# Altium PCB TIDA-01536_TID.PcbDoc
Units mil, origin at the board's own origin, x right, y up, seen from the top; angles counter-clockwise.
Board outline 2552 x 2000 mil, 2 copper layers (Top Layer, Bottom Layer), stack 62 mil thick; 52 components, 29 nets, 137 pads, 92 vias.
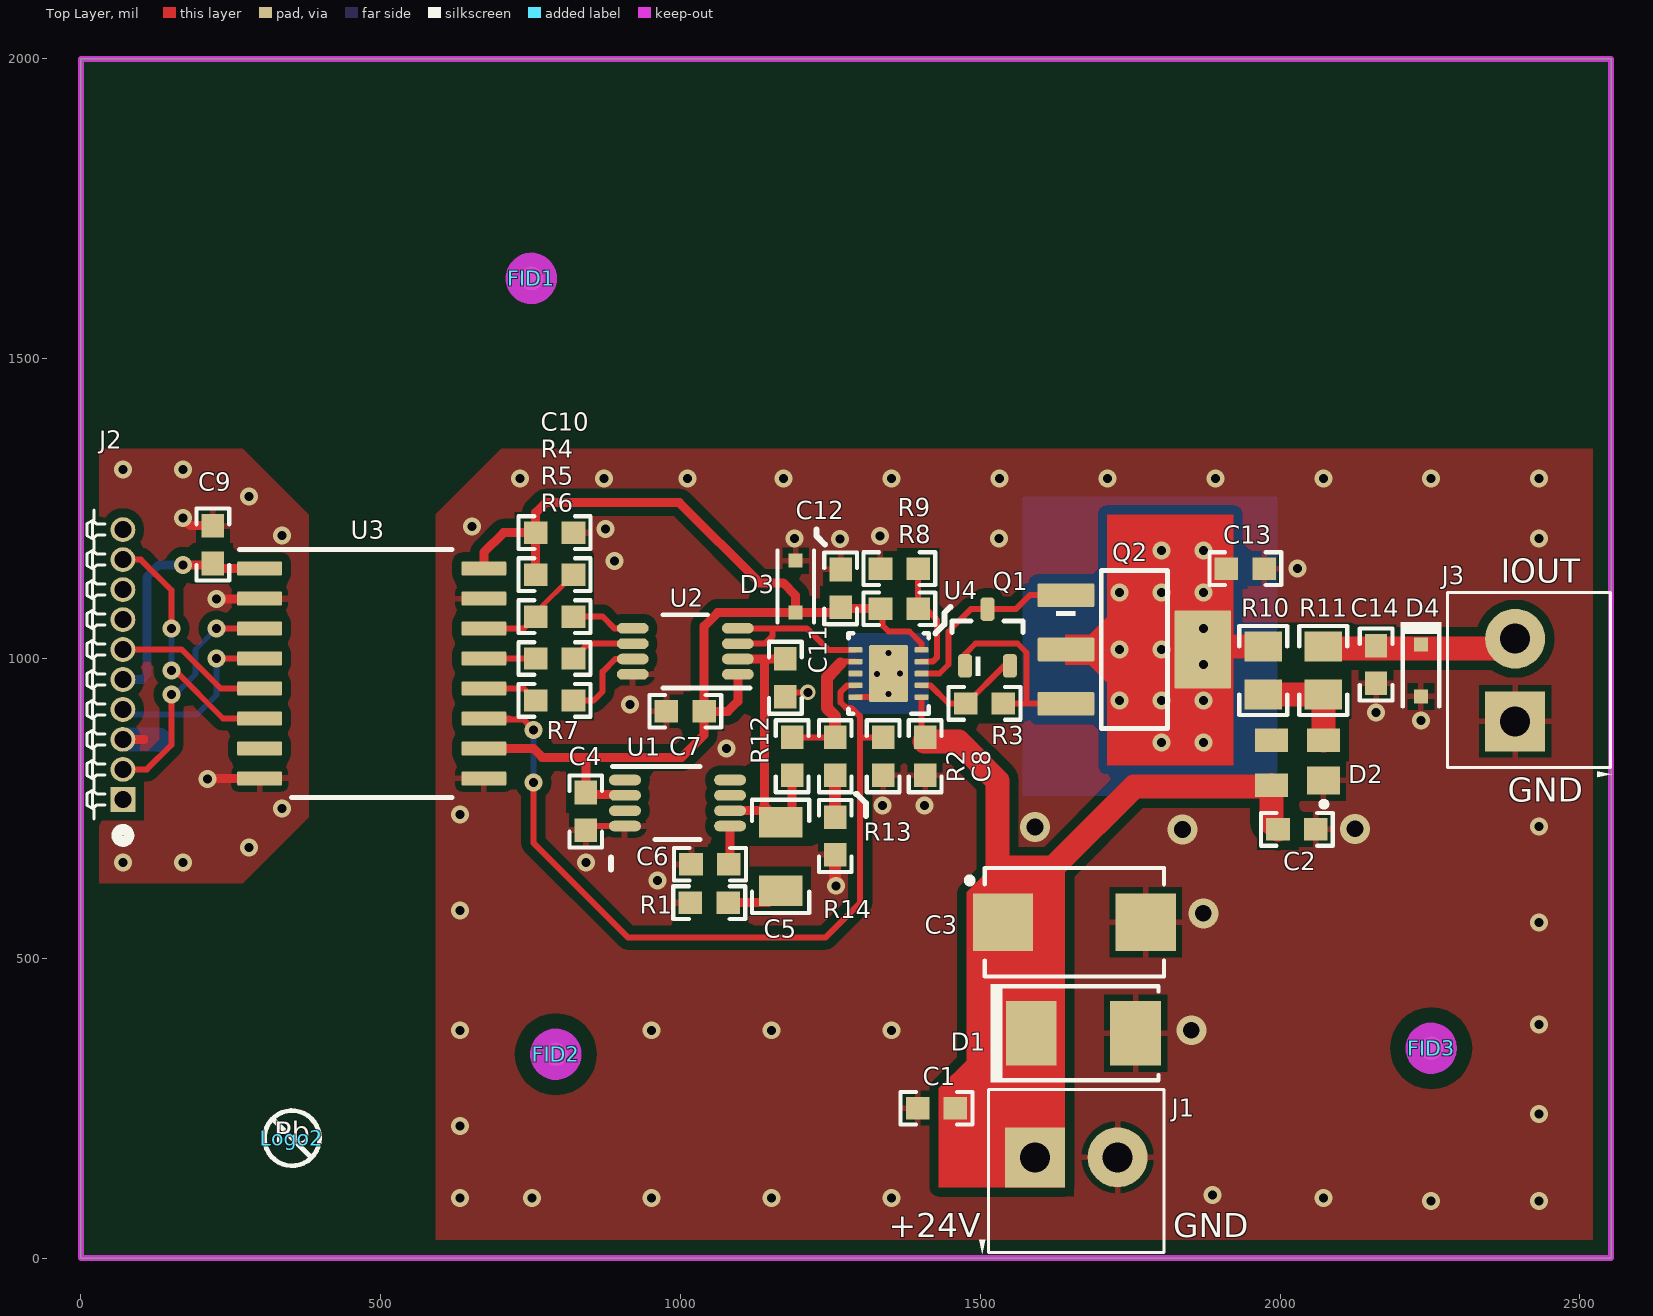
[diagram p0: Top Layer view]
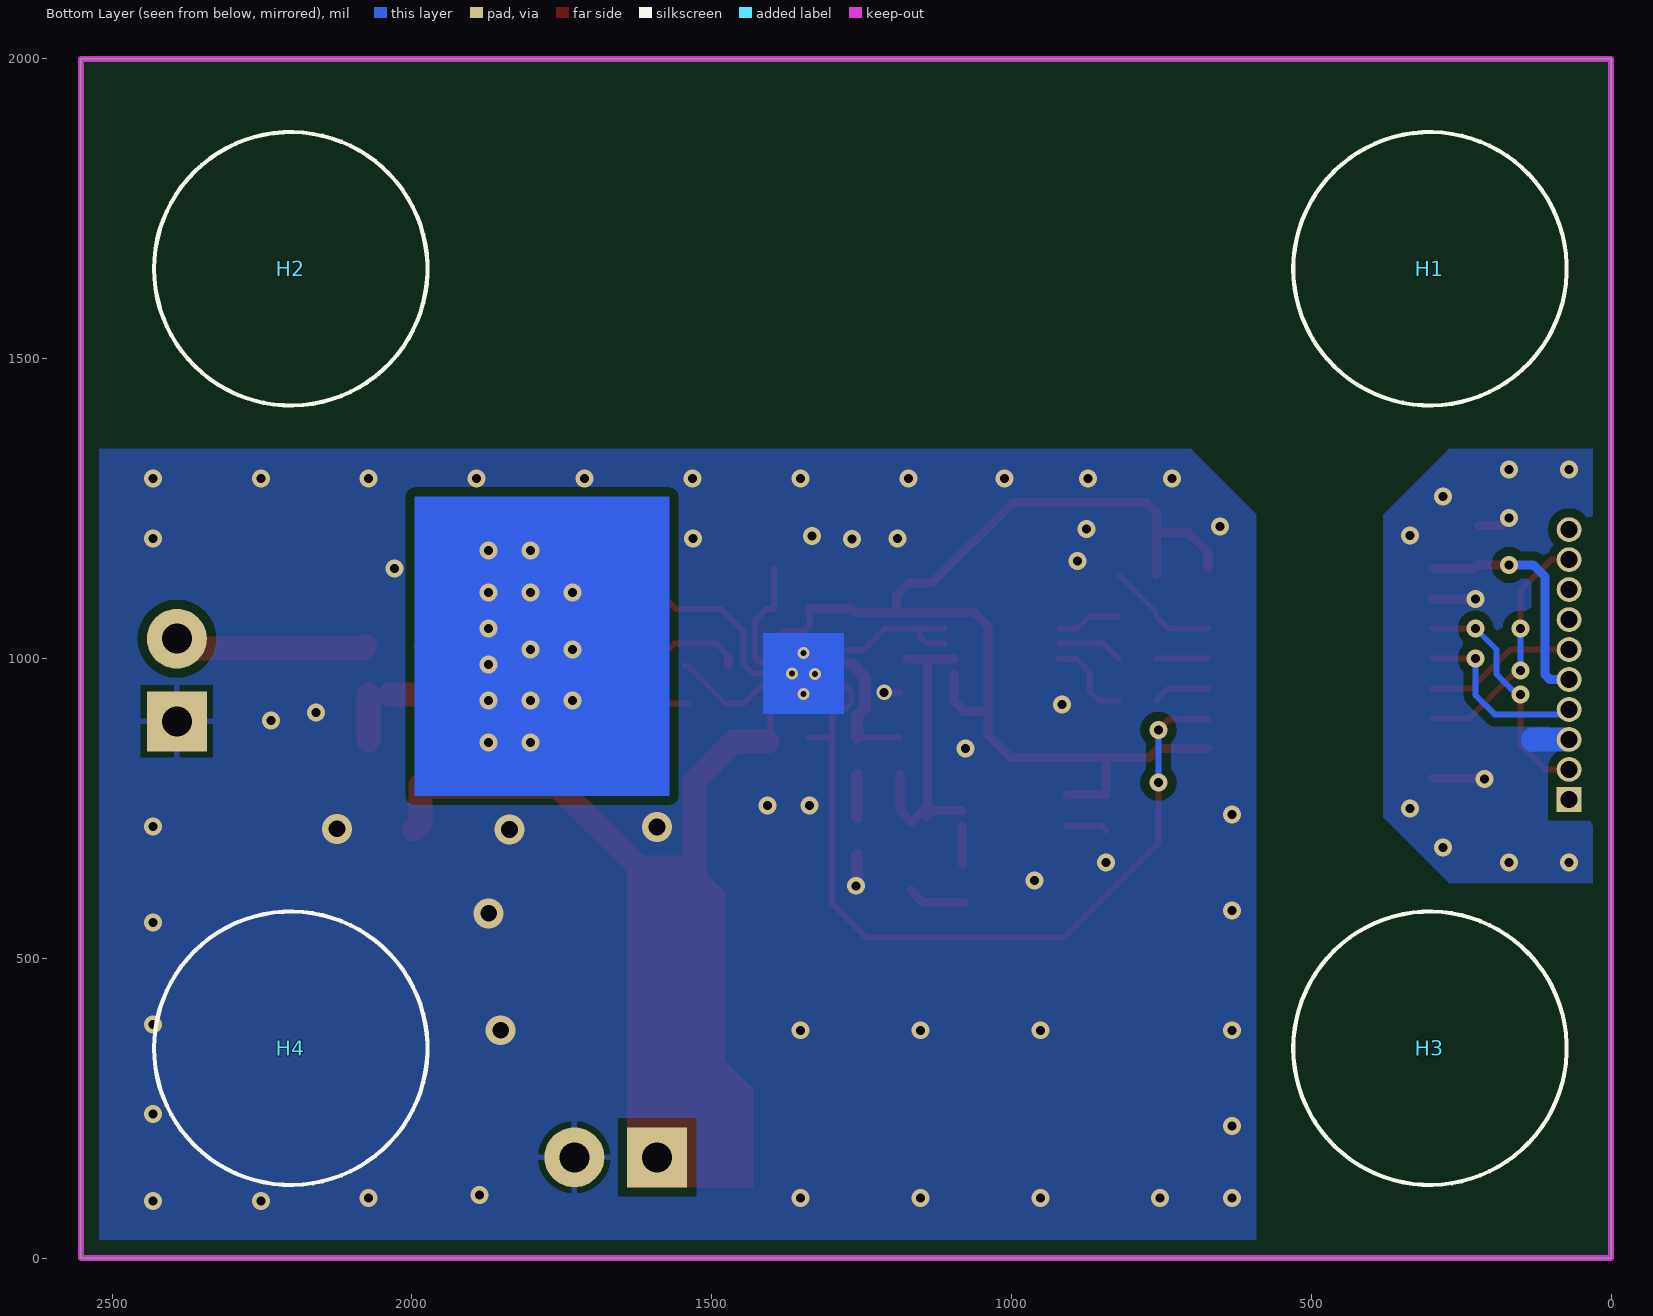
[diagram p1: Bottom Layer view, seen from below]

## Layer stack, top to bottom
Top Solder: solder mask 0.4, Solder Resist, Dk 3.5
Top Layer: signal copper 1.4
Dielectric1: core 59.2, FR-4, Dk 4.8
Bottom Layer: signal copper 1.4
Bottom Solder: solder mask 0.4, Solder Resist, Dk 3.5

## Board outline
0,0 0,2000 2552,2000 2552,0

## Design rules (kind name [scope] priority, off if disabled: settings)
AcuteAngle [All] p1: minimum=4.50000000000000E+0001 checktracksonly=FALSE
AssemblyTestPointUsage [All] p1: valid=2
Clearance Clearance_Keepouts [((IsTrack Or IsArc) And Not InPoly) And IsFree and IsKeepOut vs ((IsTrack Or IsArc) And Not InPoly) And IsFree and IsKeepOut] p1: gap=0 ignorepadtopadclearanceinfootprint=FALSE
Clearance Clearance_BoardEdge_MountingHoles [OnCopper and InComponentClass('Mounting Holes') vs IsKeepOut] p2: gap=40 ignorepadtopadclearanceinfootprint=FALSE except(0: Arc-Hole Track-Hole SMDPad-Hole THPad-Hole Via-Hole Fill-Hole Poly-Hole Region-Hole Text-Hole)
Clearance Clearance_BoardEdge_Poly [OnCopper and InPoly vs IsKeepOut] p3: gap=25 ignorepadtopadclearanceinfootprint=FALSE except(0: Arc-Hole Track-Hole SMDPad-Hole THPad-Hole Via-Hole Fill-Hole Poly-Hole Region-Hole Text-Hole)
Clearance Clearance_BoardEdge [OnCopper and Not InComponentClass('Logo') and not InComponentClass('FiducialMark') and not InRegion(1000,500,4000,800) and Not IsKeepout vs IsKeepOut] p4: gap=75 ignorepadtopadclearanceinfootprint=FALSE except(0: Arc-Hole Track-Hole SMDPad-Hole THPad-Hole Via-Hole Fill-Hole Poly-Hole Region-Hole Text-Hole)
Clearance Clearance_Poly [InPolygon] p5: gap=15 ignorepadtopadclearanceinfootprint=FALSE except(0: Arc-Hole Track-Hole SMDPad-Hole THPad-Hole Via-Hole Fill-Hole Poly-Hole Region-Hole Text-Hole)
Clearance [All] p6: gap=7.87 ignorepadtopadclearanceinfootprint=FALSE except(0: Arc-Hole Track-Hole SMDPad-Hole THPad-Hole Via-Hole Fill-Hole Poly-Hole Region-Hole Text-Hole)
ComponentClearance ComponentClearance_MountingHoles_FiducialMarks [InComponentClass('Mounting Holes') vs InComponentClass('FiducialMark')] p1: gap=50 collisioncheckmode=3 verticalgap=10 showdistances=FALSE
ComponentClearance ComponentClearance_Shunt [InComponentClass('Header') vs InComponentClass('Shunt')] p2: gap=0 collisioncheckmode=3 verticalgap=0 showdistances=FALSE
ComponentClearance ComponentClearance_Logo [InComponentClass('Logo')] p3: gap=50 collisioncheckmode=3 verticalgap=10 showdistances=FALSE
ComponentClearance ComponentClearance_ScrewToNut [(HasFootprint('NY PMS 440 0025 PH')) vs (HasFootprint('Keystone_1902C'))] p4: gap=5 collisioncheckmode=3 verticalgap=10 showdistances=FALSE
ComponentClearance ComponentClearance_MountingHoles [InComponentClass('Mounting Holes')] p5: gap=250 collisioncheckmode=3 verticalgap=100000 showdistances=FALSE
ComponentClearance ComponentClearance_SmallPassives [HasFootprint('0201*') or HasFootprint('0402*') or HasFootprint('0508') or HasFootprint('0603*') or HasFootprint('0612') or HasFootprint('0805*') or HasFootprint('0815*') or HasFootprint('0830*') or HasFootprint('1206*') or HasFootprint('1210*') or HasFootprint('1808*') or HasFootprint('1812*') or HasFootprint('1825*') or HasFootprint('2010*') or HasFootprint('2220*') or HasFootprint('2225*') or HasFootprint('2512*') or HasFootprint('2728*') or HasFootprint('3518*') vs HasFootprint('0201*') or HasFootprint('0402*') or HasFootprint('0508') or HasFootprint('0603*') or HasFootprint('0612') or HasFootprint('0805*') or HasFootprint('0815*') or HasFootprint('0830*') or HasFootprint('1206*') or HasFootprint('1210*') or HasFootprint('1808*') or HasFootprint('1812*') or HasFootprint('1825*') or HasFootprint('2010*') or HasFootprint('2220*') or HasFootprint('2225*') or HasFootprint('2512*') or HasFootprint('2728*') or HasFootprint('3518*')] p6: gap=20 collisioncheckmode=3 verticalgap=10 showdistances=FALSE
ComponentClearance ComponentClearance_THtoSMT [IsThruComponent vs IsSMTComponent] p7: gap=20 collisioncheckmode=3 verticalgap=30 showdistances=FALSE
ComponentClearance ComponentClearance_THtoTH [IsThruComponent vs IsThruComponent] p8: gap=20 collisioncheckmode=3 verticalgap=30 showdistances=FALSE
ComponentClearance [All] p9: gap=20 collisioncheckmode=3 verticalgap=10 showdistances=FALSE
DiffPairsRouting [All] p1: maxlimit=100 minlimit=10 mostfreqgap=10 toplayer_minwidth=15 toplayer_maxwidth=15 toplayer_prefwidth=15 bottomlayer_minwidth=15 bottomlayer_maxwidth=15 bottomlayer_prefwidth=15 maxuncoupledlength=1000
FabricationTestPointUsage TestPointUsage [All] p1: valid=2 allowmultiple=FALSE
FabricationTestpoint Testpoint [All] p1: side=3 testpointundercomponent=TRUE minsize=40 maxsize=100 preferedsize=60 minholesize=0 maxholesize=40 preferedholesize=32 testpointgrid=1 allowsidetop=TRUE allowsidebottom=TRUE usegrid=TRUE gridtolerance=0.01
FanoutControl Fanout_LCC [IsLCC] p1: bgadir=Out bgaviamode=Centered fanoutstyle=Auto fanoutdirection=Alternating viagrid=1 // Fanout_LCC (Default Rule)
FanoutControl Fanout_BGA [IsBGA] p2: bgadir=Out bgaviamode=Centered fanoutstyle=Auto fanoutdirection=Alternating viagrid=1 // Fanout_BGA (Default Rule)
FanoutControl Fanout_Default [All] p4: bgadir=Out bgaviamode=Centered fanoutstyle=Auto fanoutdirection=Alternating viagrid=1 // Fanout_Default (Default Rule)
FanoutControl Fanout_Small [(CompPinCount < 5)] p5: bgadir=Out bgaviamode=Centered fanoutstyle=Auto fanoutdirection=OutThenIn viagrid=1 // Fanout_Small (Default Rule)
HoleSize [All] p1: absolutevalues=TRUE maxlimit=251 minlimit=8 maxpercent=80.000 minpercent=20.000
MinimumAnnularRing MinimumAnnularRing_ThermalPadVias [IsVia and InAnyComponent] p1: minimumring=5.91
MinimumAnnularRing [All] p2: minimumring=9
MinimumSolderMaskSliver MinimumSolderMaskSliver_Logo [InComponentClass('Logo') vs InComponentClass('Logo')] p1: minsoldermaskwidth=0.7
MinimumSolderMaskSliver [All] p2: minsoldermaskwidth=3.94
PlaneConnect [All] p1: planeconnectstyle=Relief reliefexpansion=10 reliefentries=4 reliefconductorwidth=10 reliefairgap=10
PolygonConnect PolygonConnect_1 [(InComponentClass('All Components'))] p1: connectstyle=Relief reliefconductorwidth=10 reliefentries=4 polygonreliefangle="90 Angle" airgapwidth=10
PolygonConnect [All] p2: connectstyle=Direct reliefconductorwidth=10 reliefentries=4 polygonreliefangle="90 Angle" airgapwidth=10
RoutingVias ThermalPadVias [IsVia and InAnyComponent] p1: holewidth=7.87 width=19.68 viastyle="Through Hole" minholewidth=7.87 minwidth=19.68 maxholewidth=12.99 maxwidth=23.62
RoutingVias [All] p2: holewidth=16 width=34 viastyle="Through Hole" minholewidth=7.87 minwidth=26 maxholewidth=40 maxwidth=65
SilkToBoardRegionClearance [Not ((IsComment or IsDesignator) And (Hide <> 'False')) and not InRegion(1000,500,4000,800)] p1:
SilkToSilkClearance SilkToSilkClearance_Pb-FreeLogo [(HasFootprint('Pb-Free_Overlay_Medium') OR HasFootprint('Pb-Free_Overlay_Small')) vs (HasFootprint('Pb-Free_Overlay_Medium') OR HasFootprint('Pb-Free_Overlay_Small'))] p1: silktosilkclearance=0
SilkToSilkClearance [All] p2: silktosilkclearance=4
SilkToSolderMaskClearance SilkToComonentPadClearance [IsPad and InAnycomponent] p1: minsilkscreentomaskgap=5 clearancetoexposedcopper=TRUE
SilkToSolderMaskClearance "Silk to Solder Mask Opening" [All] p2: minsilkscreentomaskgap=4 clearancetoexposedcopper=FALSE
SolderMaskExpansion [All] p1: expansion=1.97
Width [All] p1: maxlimit=100 minlimit=6 preferedwidth=10 checkconnectedcopper=TRUE
15 further rules are at their usual default settings.

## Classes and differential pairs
component class TIDA-01536_BlankSheet: C1 C2 C3 C4 C5 C6 C7 C8 C9 C10 C11 C12 C13 C14 D1 D2 D3 D4 J1 J2 J3 Q1 Q2 R1 R2 R3 R4 R5 R6 R7 R8 R9 R10 R11 R12 R13 R14 U1 U2 U3 U4
component class AssemblyNote: ZZ1 ZZ2 ZZ3
component class FiducialMark: FID1 FID2 FID3
component class TIPD203_TID_Hardware: FID1 FID2 FID3 H1 H2 H3 H4 Logo2 ZZ1 ZZ2 ZZ3

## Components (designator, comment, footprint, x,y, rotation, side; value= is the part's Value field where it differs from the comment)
C1 "GRM188R71H104KA93D" 0603 1427,250 r0 top value=0.1uF
C2 "06035A101JAT2A" 0603 2028,715 r0 top value=100pF
C3 "293D106X9050E2TE3" 7343-43 1657,560 r0 top value=10uF
C4 "GRM188R71E105KA12D" 0603 842,745 r270 top value=1uF
C5 "GRM31CR61C226ME15L" 1206 1167,670 r270 top value=22uF
C6 "GRM188R71E105KA12D" 0603 1049,657 r180 top value=1uF
C7 "GRM188R71E105KA12D" 0603 1008,912 r180 top value=1uF
C8 "GRM188R71E105KA12D" 0603 1408,837 r270 top value=1uF
C9 "GRM188R71E105KA12D" 0603 220,1190 r90 top value=1uF
C10 "GRM188R71E105KA12D" 0603 790,1210 r0 top value=1uF
C11 "GRM188R71E105KA12D" 0603 1175,968 r270 top value=1uF
C12 "GRM188R71E105KA12D" 0603 1267,1117 r90 top value=1uF
C13 "GRM188R72A103KA01D" 0603 1942,1150 r0 top value=0.01uF
C14 "GRM188R71H104KA93D" 0603 2160,990 r270 top value=0.1uF
D1 "SMBJ24A-13-F" SMB 1672,375 r0 top value=24V
D2 "CD143A-SR70" SOT-143-4 2029,832 r180 top
D3 "CDSOD323-T05" SOD-323-Bi 1192,1120 r270 top value=5V
D4 "CDSOD323-T24S" sod-323 2235,980 r270 top
FID1 "Fiducial" Fiducial10-20 751,1634 r0 top
FID2 "Fiducial" Fiducial10-20 792,340 r0 top
FID3 "Fiducial" Fiducial10-20 2252,350 r0 top
H1 "SJ-5303 (CLEAR)" Bumpon_SJ5003Transparent 302,1650 r180 bottom
H2 "SJ-5303 (CLEAR)" Bumpon_SJ5003Transparent 2202,1650 r180 bottom
H3 "SJ-5303 (CLEAR)" Bumpon_SJ5003Transparent 302,350 r180 bottom
H4 "SJ-5303 (CLEAR)" Bumpon_SJ5003Transparent 2202,350 r180 bottom
J1 "ED555/2DS" TERM_BLK_ED555-2DS 1591,168 r0 top
J2 "SUPER MINI DIG FEMALE" CONN_851-43-010-20-001000 70,990 r270 top
J3 "ED555/2DS" TERM_BLK_ED555-2DS 2392,895 r90 top
Logo2 "Pb-Free Symbol" Pb-Free_Overlay_Small 352,200 r0 top
Q1 "BC856B-7-F" SOT-23 1512,1035 r90 top value="65 V"
Q2 "NDT2955" SOT-223 1757,1015 r0 top value=-60V
R1 "CRCW06031R00JNEA" 0603 1048,593 r0 top value=1.0
R2 "CRCW0603100KFKEA" 0603 1338,837 r90 top value=100k
R3 "CRCW060315R0FKEA" 0603 1507,925 r0 top value=15.0
R4 "RC0603FR-0710KL" 0603 790,1140 r180 top value=10.0k
R5 "CRCW060333R0FKEA" 0603 790,1070 r0 top value=33.0
R6 "CRCW060333R0FKEA" 0603 790,1000 r0 top value=33.0
R7 "CRCW060333R0FKEA" 0603 790,930 r0 top value=33.0
R8 "RG1608P-8251-B-T5" 0603 1365,1083 r0 top value=8.25k
R9 "RG1608P-103-B-T5" 0603 1365,1150 r180 top value=10.0k
R10 "CRCW080515R0FKEA" 0805_HV 1972,980 r270 top value=15.0
R11 "CRCW080515R0FKEA" 0805_HV 2072,980 r90 top value=15.0
R12 "RG1608P-3093-B-T5" 0603 1186,837 r270 top value=309k
R13 "RG1608P-2431-B-T5" 0603 1258,837 r90 top value=2.43k
R14 "2-1676481-2" 0603 1258,704 r90 top value=39.0
U1 "REF5050AIDGKT" DGK0008A_N 995,759 r0 top
U2 "DAC8551IDGKR" DGK0008A_N 1008,1012 r180 top
U3 "ISO7340CDWR" DW0016B_N 485,975 r0 top
U4 "XTR111AIDRCT" DRC0010A 1347,975 r180 top
ZZ1 "These assemblies are ESD sensitive, ESD precautions shall be observed." AssemblyNote 137,3829.11 r0 top
ZZ2 "These assemblies must be clean and free from flux and all contaminants. Use of no clean flux is not acceptable." AssemblyNote 137,3740.56 r0 top
ZZ3 "These assemblies must comply with workmanship standards IPC-A-610 Class 2, unless otherwise specified." AssemblyNote 137,3652 r0 top

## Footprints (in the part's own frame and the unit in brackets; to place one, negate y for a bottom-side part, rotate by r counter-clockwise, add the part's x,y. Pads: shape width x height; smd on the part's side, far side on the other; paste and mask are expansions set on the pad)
0603 [mm] "0603 from SM-752 data"
  rect 1x0.95 smd: 1(-0.8,0) 2(0.8,0)
  silkscreen extent -1.52,-0.69 1.52,0.69, body extent -0.87,-0.47 0.87,0.47, height 1
0805_HV [mil] "0805 with 30mil clearance between pads"
  rect 50x63 smd: 1(-40,0) 2(40,0)
  silkscreen extent -74,-40 74,40, body extent -43,-29 43,29, height 57
1206 [mm] "1206 from SM-752 data"
  rect 1.3x1.85 smd: 1(-1.45,0) 2(1.45,0)
  silkscreen extent -2.4,-1.21 2.4,1.21, body extent -1.7,-0.9 1.7,0.9, height 1.35
7343-43 [mm] "Medium density IPC based on Kemet T495 series"
  rect 2.55x2.45 smd: 1(-3.025,0) 2(3.025,0)
  silkscreen extent -4.56,-2.3 3.8,2.3, body extent -3.8,-2.3 3.8,2.3, height 4.3
AssemblyNote [mil] "Assembly Note"
Bumpon_SJ5003Transparent [mil] "3M Hemispherical Bumpon transparent"
  round 1 on Mech4: 0(0,0)
  silkscreen extent -228,-228 228,228, body extent -217,-218 219,218, height 197
CONN_851-43-010-20-001000 [mm] "Mill-max"
  rect 1.05x1.05 hole 0.73 mask+0.06: 1(5.715,0)
  round 1.05 hole 0.73 mask+0.06: 2(4.445,0) 3(3.175,0) 4(1.905,0) 5(0.635,0) 6(-0.635,0) 7(-1.905,0) 8(-3.175,0) 9(-4.445,0) 10(-5.715,0)
  silkscreen extent -6.54,-1.52 7.49,0.25, body extent -6.54,-5.31 6.54,0.23, height 2.23
DGK0008A_N [mm] "TSOP, 8-Leads, Body 3x3mm, Pitch 0.65mm, IPC Medium Density"
  oval 1.35x0.45 smd: 1(-2.225,0.975) 2(-2.225,0.325) 3(-2.225,-0.325) 4(-2.225,-0.975) 5(2.225,-0.975) 6(2.225,-0.325) 7(2.225,0.325) 8(2.225,0.975)
  silkscreen extent -2.75,-1.55 0.95,1.55, body extent -2.45,-1.5 2.45,1.5, height 0.96
DRC0010A [mm] "SON, 10-Leads, Body 3x3mm, Pitch 0.5mm, Thermal Pad 2.4x1.65mm, TI Recommended"
  rrect42% 0.6x0.24 smd: 1(-1.4,1) 2(-1.4,0.5) 3(-1.4,0) 4(-1.4,-0.5) 5(-1.4,-1) 6(1.4,-1) 7(1.4,-0.5) 8(1.4,0) 9(1.4,0.5) 10(1.4,1)
  rrect6% 1.65x2.4 smd paste-0.825: 11(0,0)
  silkscreen extent -1.7,-1.7 1.7,1.7, body extent -1.55,-1.55 1.55,1.55, height 1.01
DW0016B_N [mm] "SOIC, 16-Leads, Body 10.5x7.6mm, Pitch 1.27mm, IPC Medium Density"
  rrect17% 1.9x0.6 smd: 1(-4.75,4.445) 2(-4.75,3.175) 3(-4.75,1.905) 4(-4.75,0.635) 5(-4.75,-0.635) 6(-4.75,-1.905) 7(-4.75,-3.175) 8(-4.75,-4.445) 9(4.75,-4.445) 10(4.75,-3.175) 11(4.75,-1.905) 12(4.75,-0.635) 13(4.75,0.635) 14(4.75,1.905) 15(4.75,3.175) 16(4.75,4.445)
  silkscreen extent -5.6,-5.25 3.4,5.25, body extent -5.17,-5.15 5.17,5.15, height 2.59
Fiducial10-20 [mm]
  round 1 smd mask+0.5: 1(0,0)
  Top Layer keep-out circle w1.178: c0,0 r0.5
Pb-Free_Overlay_Small [mil]
  silkscreen extent -46,-46 46,46
SMB [mil] "Molded Diode, 2-Leads, Body 5.4x3.6mm, IPC Medium Density, based on OnSemi component dimensions"
  rect 85x107.99 smd: 1(-87.01,0) 2(87.01,0)
  silkscreen extent -155,-82 125,82, body extent -106,-71 106,71, height 91
sod-323 [mm] "NXP recommended land pattern"
  rect 0.6x0.6 smd paste-0.05: 1(-1.1,0) 2(1.1,0)
  silkscreen extent -2.06,-0.86 1.53,0.86, body extent -1.3,-0.67 1.3,0.68, height 1.1
SOD-323-Bi [mm] "SOD323, 2-Leads, Body 1.9x1.45mm, No Polarity Mark"
  rect 0.6x0.6 smd paste-0.05: 1(-1.1,0) 2(1.1,0)
  silkscreen extent -1.53,-0.77 1.53,0.77, body extent -1.27,-0.65 1.27,0.65, height 1.02
SOT-23 [mm] "SOT23, 3-Leads, Body 2.9x1.3mm, Pitch 0.95mm, Lead Span 2.5mm, IPC Medium Density"
  rrect50% 1x0.6 smd: 1(-1.2,0.95) 2(-1.2,-0.95) 3(1.2,0)
  silkscreen extent -1.63,-1.5 0.7,1.5, body extent -1.16,-1.45 1.21,1.45, height 1
SOT-143-4 [mm] "Littelfuse"
  rect 1.4x1.2 smd: 1(-1.1,0.9)
  rect 1.4x1 smd: 2(-1.1,-0.8) 3(1.1,-0.8) 4(1.1,1.1)
  silkscreen extent -1.22,1.8 -1.02,2.01, body extent -0.7,-1.37 0.7,1.67, height 1.23
SOT-223 [mm] "SOT223/SC73, 4-Leads, Body 6.5x3.5mm, Pitch 2.3mm, Lead Span 7mm, IPC Medium Density"
  rrect10% 2.4x1 smd: 1(-2.9,2.3) 2(-2.9,0) 3(-2.9,-2.3)
  rrect4% 2.4x3.3 smd: 4(2.9,0)
  silkscreen extent -3.32,-3.35 1.4,3.35, body extent -3.5,-3.25 3.5,3.25, height 1.62
TERM_BLK_ED555-2DS [mil]
  rect 100x100 hole 50: 1(0,0)
  round 100 hole 50: 2(138,0)
  silkscreen extent -93,-161 215,113, body extent -69,-150 207,106, height 323

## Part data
C1 C14: "CAP, CERM, 0.1uF, 50V, +/-10%, X7R, 0603", Alternate Manufacturer=-, Cap_Case=0603, Manufacturer=MuRata, Supplier Part Number 1=490-1519-1-ND, TempCo=X7R, Tolerance_%=10, Value1=?, Value2=50V, ValueDisplayed=0.1µF
C2: "CAP, CERM, 100pF, 50V, +/-5%, C0G/NP0, 0603", Alternate Manufacturer=-, Cap_Case=0603, Manufacturer=AVX, Supplier Part Number 1=478-1175-1-ND, TempCo=C0G/NP0, Tolerance_%=5, Value1="0.119 ohm", Value2=50V, ValueDisplayed=100pF
C3: "CAP, TANT, 10uF, 50V, +/-10%, 0.8 ohm, 7343-43 SMD", Alternate Manufacturer=-, Cap_Case=E, Manufacturer=Vishay-Sprague, Supplier Part Number 1=718-1022-1-ND, Tolerance_%=10, Value1="0.8 ohm", Value2=50V, ValueDisplayed=10µF
C4 C6 C7 C8 C9 C10 C11 C12: "CAP, CERM, 1 µF, 25 V, +/- 10%, X7R, 0603", Cap_Case=0603, Manufacturer=MuRata, Supplier Part Number 1=490-5307-1-ND, TempCo=X7R, Tolerance_%=10, Value1=Unknown, Value2=25V, ValueDisplayed=1µF
C5: "CAP, CERM, 22 µF, 16 V, +/- 20%, X5R, 1206", Cap_Case=1206, Manufacturer=MuRata, Supplier Part Number 1=490-4739-1-ND, TempCo=X5R, Tolerance_%=20, Value1="0.006 ohm", Value2=16V, ValueDisplayed=22µF
C13: "CAP, CERM, 0.01 µF, 100 V, +/- 10%, X7R, 0603", Cap_Case=0603, Manufacturer=MuRata, Supplier Part Number 1=GRM188R72A103KA01D-ND, TempCo=X7R, Tolerance_%=10, Value1=Unknown, Value2=100V, ValueDisplayed=0.01µF
D1: "Diode, TVS, Uni, 24 V, 600 W, SMB", Manufacturer="Diodes Inc.", Power_W=5, Supplier Part Number 1=SMBJ24A-FDICT-ND, Value1=5W
D2: "IC TVS ARRAY 2-LINE 70V SOT-143", Alternate Manufacturer=-, Manufacturer=Bourns, Supplier Part Number 1=CD143A-SR70CT-ND
D3: library part CDSOD323-T05C, "TVS DIODE 5VWM 9.8VC SOD323", Manufacturer=Bourns, Power_W=350, Supplier Part Number 1=CDSOD323-T05CT-ND, Value1=350W
D4: library part SMAJ15CA, "TVS DIODE 24VWM 43VC SMD", Alternate Manufacturer=-, Manufacturer=Bourns, Supplier Part Number 1=CDSOD323-T24S-ND
FID1 FID2 FID3: "Fiducial mark.  There is nothing to buy or mount.", Manufacturer=N/A
H1 H2 H3 H4: "Bumpon, Hemisphere, 0.44 X 0.20, Clear", Manufacturer=3M, Supplier Part Number 1=SJ5303-7-ND
J1 J3: "Terminal Block, 6A, 3.5mm Pitch, 2-Pos, TH", Manufacturer="On-Shore Technology", Supplier Part Number 1=ED1514-ND
J2: library part 851-43-010-20-001000, "Receptacle, 50mil 10x1, R/A, TH", Manufacturer=Mill-Max
Logo2: library part Pb-Free
Q1: library part "BC856B-7-F, Diodes Inc.", "Transistor, PNP, 65 V, 0.1 A, SOT-23", Manufacturer="Diodes Inc.", Supplier Part Number 1=BC856B-7FDICT-ND, Value1="0.1 A", Value2=330
Q2: "MOSFET, P-CH, -60 V, -2.5 A, SOT-223", Alternate Manufacturer=None, Manufacturer="Fairchild Semiconductor", Supplier Part Number 1=NDT2955CT-ND, Value1="0.5 ohm", Value2="11 nC"
R1: "RES, 1.0, 5%, 0.1 W, 0603", Manufacturer=Vishay-Dale, Power_W=0.1, Supplier Part Number 1=541-1.0GCT-ND, TempCo="200 ppm/C", Tolerance_%=5, Value1=5%, Value2=0.1W, Value_Code=1R00, ValueDisplayed=1.0
R2: "RES, 100 k, 1%, 0.1 W, 0603", Manufacturer=Vishay-Dale, Power_W=0.1, Supplier Part Number 1=541-100KHCT-ND, TempCo="100 ppm/C", Tolerance_%=1, Value1=1%, Value2=0.1W, Value_Code=100k
R3: "RES, 15.0, 1%, 0.1 W, 0603", Manufacturer=Vishay-Dale, Power_W=0.1, Supplier Part Number 1=541-15.0HCT-ND, TempCo="100 ppm/C", Tolerance_%=1, Value1=1%, Value2=0.1W, Value_Code=15R0, ValueDisplayed=15.0
R4: "RES, 10.0 k, 1%, 0.1 W, 0603", Manufacturer="Yageo America", Power_W=0.1, Supplier Part Number 1=311-10.0KHRCT-ND, TempCo="200 ppm/C", Tolerance_%=1, Value1=1%, Value2=0.1W, Value_Code=10k0, ValueDisplayed=10.0k
R5 R6 R7: "RES, 33.0, 1%, 0.1 W, 0603", Manufacturer=Vishay-Dale, Power_W=0.1, Supplier Part Number 1=541-33.0HCT-ND, TempCo="100 ppm/C", Tolerance_%=1, Value1=1%, Value2=0.1W, Value_Code=33R0, ValueDisplayed=33.0
R8: "RES, 8.25 k, 0.1%, 0.1 W, 0603", Manufacturer="Susumu Co Ltd", Power_W=0.1, Supplier Part Number 1=RG16P8.25KBCT-ND, TempCo="25 ppm/C", Value1=0.1%, Value2=0.1W, Value_Code=8k25, ValueDisplayed=8.25k
R9: "RES, 10.0 k, 0.1%, 0.1 W, 0603", Manufacturer="Susumu Co Ltd", Power_W=0.1, Supplier Part Number 1=RG16P10.0KBCT-ND, TempCo="25 ppm/C", Value1=0.1%, Value2=0.1W, Value_Code=10k0, ValueDisplayed=10.0k
R10 R11: "RES, 15.0, 1%, 0.125 W, 0805", Manufacturer=Vishay-Dale, Power_W=0.125, Supplier Part Number 1=541-15.0CCT-ND, TempCo="100 ppm/C", Tolerance_%=1, Value1=1%, Value2=0.125W, Value_Code=15R0, ValueDisplayed=15.0
R12: "RES, 309 k, 0.1%, 0.1 W, 0603", Manufacturer="Susumu Co Ltd", Power_W=0.1, Supplier Part Number 1=RG16P309KBCT-ND, TempCo="25 ppm/C", Value1=0.1%, Value2=0.1W, Value_Code=309k
R13: "RES, 2.43 k, 0.1%, 0.1 W, 0603", Manufacturer="Susumu Co Ltd", Power_W=0.1, Supplier Part Number 1=RG16P2.43KBCT-ND, TempCo="25 ppm/C", Value1=0.1%, Value2=0.1W, Value_Code=2k43, ValueDisplayed=2.43k
R14: library part RC0603FR-0739RL, "RES SMD 39 OHM 0.1% 1/16W 0603", Manufacturer="TE Connectivity", Power_W=0.1, Supplier Part Number 1=A103095CT-ND, Tolerance_%=1, Value1=0.1%, Value2=0.1W, Value_Code=39R0, ValueDisplayed=39.0
U1: "Low Noise, Very Low Drift, Precision Voltage Reference, -40 to 125 degC, 8-pin VSSOP (DGK), Green (RoHS & no Sb/Br)", Alternate Manufacturer="Texas Instruments", Alternate PartNumber=Equivalent, Rating=Catalog, Supplier Part Number 1=296-24506-2-ND, Temp Coeff(Max)(ppm/ degree C)=3
U2: "16-BIT, ULTRA-LOW GLITCH, VOLTAGE OUTPUT DIGITAL-TO-ANALOG CONVERTER, DGK0008A", Alternate Manufacturer="Texas Instruments", Alternate PartNumber=DAC8551IDGKT
U3: "Robust EMC, Low Power, Quad-Channel Digital Isolators, DW0016B", Alternate Manufacturer="Texas Instruments", Alternate PartNumber=ISO7340CDW
U4: "Precision Voltage-to-Current Converter/Transmitter, DRC0010A", Alternate Manufacturer="Texas Instruments"
ZZ1 ZZ2 ZZ3: library part AssemblyNote, Alternate Manufacturer=-

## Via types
v1: diameter 30, hole 15, Top Layer to Bottom Layer, 82 vias
v2: diameter 50, hole 28, Top Layer to Bottom Layer, 5 vias
v3: diameter 20, hole 10, Top Layer to Bottom Layer, 4 vias
v4: diameter 26, hole 15, Top Layer to Bottom Layer, 1 vias

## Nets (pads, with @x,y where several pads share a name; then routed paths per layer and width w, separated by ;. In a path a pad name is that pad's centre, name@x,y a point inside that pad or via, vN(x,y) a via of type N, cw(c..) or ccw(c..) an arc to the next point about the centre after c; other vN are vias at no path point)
+24V: C1.2 C2.1 C3.1 C8.1 D1.1 D2.4 J1.1 U4.1 | length 898.8
  Top Layer w10: C8.1@1398,868.5 C8.1@1403.12,873.61 ; C8.1@1402.12,866.61 U4.1
  Top Layer w40: C8.1@1407,861.5 1463.5,861.5 1529,796 1529,614 ; 1627,657 1756.69,786.69 1983.69,786.69 D2.4 1985.69,725.81 C2.1
/CS: J2.2 U3.3 | length 388.6
  Top Layer w10: J2.2@80,815 110,815 151,856 v1(151,940) ; v1(226,1050) U3.3
  Bottom Layer w10: v1(151,940) 157,940 191,974 191,1015 v1(226,1050)
GND: C1.1 C2.2 C3.2 C4.2 C6.2 C7.2 C8.2 C10.2 C11.2 C12.2 C13.2 C14.2 D1.2 D2.1 D3.1 D4.2 J1.2 J3.1 R1.1 R2.1 R9.2 R14.1 U1.4 U2.8 U3.9 U3.15 U4.10 U4.11 | length 178.1
  Top Layer w10: C4.2 849.11,720.61 U1.4 ; C11.2@1185,943.5 v4(1212.5,943.5) ; U4.10 U4.11@1323.63,935.63
  Top Layer w20: v1@1258,622 R14.1
  other v1: 2252,95 2432,95 632,100 752,100 952,100 1152,100 1352,100 2072,100 1887,105 632,220 2432,240 632,380 952,380 1152,380 1352,380 2432,390 2432,560 632,580 1259,621 962,630 842,660 2432,720 632,740 1337,755 1407,755 1077,850 2235,897 2160,910 916,923 2029,1150 890,1163 1266,1199 1190,1200 1531,1200 2432,1200 1333,1204 875,1216 652,1220 732,1300 872,1300 1012,1300 1172,1300 1352,1300 1532,1300 1712,1300 1892,1300 2072,1300 2252,1300 2432,1300
  other v2: 1852,380 1872,575 1837,715 2125,716 1591,719
  other v3: 1347,941 1328,974 1366,975 1347,1009
GPIO1: J2.9 U3.6 | length 416.3
  Top Layer w10: J2.9 100,1165 151,1114 v1(151,1050) ; v1(151,980) 157,980 237,900 U3.6
  Bottom Layer w10: v1(151,980) v1(151,1050)
ISO_GND: C9.2 J2.3 U3.2 U3.8 | length 310.8
  Top Layer w15: J2.3 105,865 ; v1(170,1234) 182.5,1221.5 C9.2 ; v1(211,799) 212,800 U3.8 ; v1(226,1099) 296.99,1099 U3.2
  Bottom Layer w40: J2.3 130.05,865 130.61,864.45
  other v1: 70,660 170,660 280,685 335,750 335,1205 280,1270 70,1315 170,1315
NetC5_2: C5.2 R1.2 | length 95.8
  Top Layer w15: R1.2 1147.09,593 C5.2
NetC6_1: C6.1 U1.5 | length 64.5
  Top Layer w15: C6.1 1082.6,659.1 U1.5
NetC13_1: C13.1 Q2.2 Q2.4 R10.1 | length 443
  Top Layer w40: Q2.2 Q2.4 ; v1@1867,1123.5 1867,1019.17 1875.35,1019.17 1876.17,1020 R10.1@1977,1020
  other v1: 1802,860 1872,860 1732,930 1802,930 1872,930 1872,990 1732,1015 1802,1015 1872,1050 1732,1110 1802,1110 1872,1110 1802,1180 1872,1180
NetC14_1: C14.1 D4.1 J3.2 R11.2 | length 323.1
  Top Layer w40: R11.2@2077,1020 2080.31,1016.69 2375.69,1016.69 J3.2
NetD2_2: D2.2 R10.2 R11.1 | length 136.6
  Top Layer w40: R10.2@1977,940 2037,940 ; R11.1 2072.31,939.69 D2.2
NetQ1_1: Q1.1 Q2.3 R3.2 | length 340.1
  Top Layer w10: Q1.1@1469.6,987.76 Q1.1@1469.6,1002.6 ; Q1.1 1474.6,1007.6 1492,1025 1562,1025 1577,1010 1577,925 ; R3.2 1577,925 ; Q2.3 1642.28,925 1577,925
NetQ1_2: Q1.2 R3.1 U4.2 | length 180.8
  Top Layer w10: U4.2 1416.69,955.31 1447,925 R3.1 1477,925 1539.76,987.76 Q1.2@1544.4,987.76
NetQ1_3: Q1.3 Q2.1 U4.3 | length 327
  Top Layer w10: U4.3 1432,975 1447,990 1447,1045 1484.24,1082.24 1559.24,1082.24 1582.55,1105.55 Q2.1
NetR4_1: R4.1 R5.1 U3.14 | length 190.9
  Top Layer w8: R5.1 758.5,1077.01 R4.1
  Top Layer w10: U3.14 738.5,1050 R5.1
NetR5_2: R5.2 U2.5 | length 107
  Top Layer w10: R5.2 870,1070 889.61,1050.39 U2.5
NetR6_1: R6.1 U3.13 | length 86.5
  Top Layer w10: U3.13 R6.1
NetR6_2: R6.2 U2.6 | length 109.2
  Top Layer w10: R6.2 846.29,1024.8 U2.6
NetR7_1: R7.1 U3.12 | length 94.8
  Top Layer w10: U3.12 738.5,950 R7.1
NetR7_2: R7.2 U2.7 | length 146.9
  Top Layer w10: R7.2 855,930 870,945 870,978 891.2,999.2 U2.7
NetR8_2: R8.2 R9.1 U4.4 | length 197.3
  Top Layer w10: R9.1 R8.2 1409,1083 1428,1064 1428,1002 1420.68,994.68 U4.4
NetR12_1: R12.1 R13.2 U4.7 | length 237.9
  Top Layer w10: R12.1@1188,868.5 R13.2@1249.32,868.5 ; R13.2@1250.32,876.17 R13.2 ; 1265.09,993.09 1266.68,994.68 U4.7
  Top Layer w15: 1266.41,991.77 1266.68,992.04
  Top Layer w20: R13.2 1258,903.58 1244.32,917.26 1244.32,968.35 1258,982.03 1258,982.81 1266.68,991.5
NetR13_1: R13.1 R14.2 | length 70
  Top Layer w20: R14.2 R13.1
NetU2_3: U2.3 U2.4 U4.6 | length 257
  Top Layer w10: U2.3@1110.6,1024.8 1140.8,1024.8 1153,1037 1153,1050.39 ; U2.4@1110.6,1050.39 1153,1050.39 ; U4.6 1246.63,1014.37 1210.61,1050.39 1153,1050.39
OD: R2.2 U3.11 U4.9 | length 1396
  Top Layer w10: 715,900 U3.11 672.01,898.43 737.57,898.43 v1(755,881) ; v1(755,793) 755,692 912,535 1242,535 1299,592 1299,904 1285.24,917.76 1276.18,917.76 1267.2,926.74 1267.2,944.52 1275.9,953.23 1277.31,953.23 1277.31,955.31 U4.9 ; 1300,869 1300.5,868.5 R2.2
  Bottom Layer w10: v1(755,793) v1(755,881)
SCLK: J2.4 U3.4 | length 305.6
  Top Layer w10: v1(226,1000) U3.4
  Bottom Layer w10: J2.4 78,907 194,907 226,939 v1(226,1000)
SDO: J2.6 U3.5 | length 244.9
  Top Layer w10: J2.6@80,1015 168,1015 233,950 U3.5
VDUT: C9.1 J2.5 U3.1 | length 408.6
  Top Layer w15: v1(170,1156) C9.1@222.5,1156 ; C9.1 C9.1@222.5,1156 ; U3.1 228.5,1150 C9.1@222.5,1156
  Bottom Layer w10: J2.5 J2.5@82.5,965
  Bottom Layer w15: J2.5@82.5,965 102,965 110,973 110,1136 130,1156 v1(170,1156)
VREF: C5.1 C11.1 R12.2 U1.6 U2.2 | length 535
  Top Layer w15: U1.6 C5.1@1147.88,746.2 ; U2.2 1140,999.2 ; 1139,755.09 C5.1@1147.88,746.2 ; C5.1@1140,736.09 1140,999.2 ; C11.1@1174.29,999.2 1140,999.2 ; R12.2@1186,807.5 1186,746.09 C5.1 C5.1@1147.88,746.2
VREG: C4.1 C7.1 C10.1 C12.1 D3.2 R4.2 R8.1 U1.2 U2.1 U3.10 U3.16 U4.5 | length 1997.5
  Top Layer w10: R8.1@1337,1083.5 1337,1054.98 1346.98,1045 1382,1045 1402.12,1024.88 U4.5
  Top Layer w15: U3.10 754,850 ; U3.16 672.01,1177.01 705,1210 C10.1 ; 755,850 754,850 ; R4.2 C10.1 ; U1.2 906.04,773.15 842,773.15 C4.1 842,835 ; U2.1 1095.6,928.6 1079,912 C7.1 ; R8.1@1337,1083.5 1267,1083.5 1260.19,1076.69 D3.2 ; 754,850 769,835 842,835 ; C10.1 758.5,1243.5 775,1260 997.98,1260 1132,1125.98 1171.02,1125.98 1192,1105 D3.2 ; 842,835 1002,835 1039.5,872.5 C7.1 ; C7.1 1039.5,1054.19 1062,1076.69 D3.2
pads on no net: D2.3 FID1.1 FID2.1 FID3.1 H1.0 H2.0 H3.0 H4.0 J2.1 J2.7 J2.8 J2.10 U1.1 U1.3 U1.7 U1.8 U3.7 U4.8

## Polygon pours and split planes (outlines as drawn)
GND on Top Layer "Top_GND" (solid, remove dead copper, pour order 10): 592,0 592,1241 701,1350 707,1350 2552,1350 2552,5 2552,0
ISO_GND on Top Layer "Top_ISOGND" (solid, remove dead copper, pour order 8): 0,1350 270,1350 380,1240 380,735 270,625 0,625
GND on Bottom Layer "Bot_GND" (solid, remove dead copper, pour order 9): 592,0 592,1241 701,1350 707,1350 2552,1350 2552,5 2552,0
ISO_GND on Bottom Layer "Bot_ISOGND" (solid, remove dead copper, pour order 11): 0,1350 270,1350 380,1240 380,735 270,625 0,625

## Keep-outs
Keep-Out Layer:
  the board outline again, w10
  text ".Layer_Name" at 529,-858.49 h60

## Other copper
Top Layer:
  region net +24V: 1431,118 1641,118 1641,671 1537.45,671 1477,610.55 1477,329 1431,283
  region net NetC13_1: 1642,1040 1682,1040 1712,1070 1712,1240 1922,1240 1922,822 1712,822 1712,960 1682,990 1642,990
  text ".Layer_Name" at 529,-858.49 h60
Bottom Layer:
  region net GND: 1280.07,1041.93 1413.93,1041.93 1413.93,908.07 1280.07,908.07
  region net NetC13_1: 1571,1270 1995,1270 1995,771 1571,771
  text ".Layer_Name" at 529,-858.49 h60

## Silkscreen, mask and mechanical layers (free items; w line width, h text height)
Top Overlay:
  lines w10: 884,648 884,668 ; 1227,1215 1227,1204 1241,1190 ; 1293,774 1294,774 1309,759 1309,737 ; 1425,1042 1440,1057 1440,1076 1450,1086
  text "This document can handle board shapes up to 7.9in x 10in, although" at 5252,2655 h60
  text "our panel vendors top out at 7in x 10in." at 5252,2530.94 h60
  text "To re-size the board shape, do the following:" at 5307,2406.88 h60
  text "Select lines on M1 Board Outline and delete (easy in single layer mode...shift+s)" at 5367,2282.82 h60
  text "Draw a rectangle using lines (example will be for a 4\" x 6\" board" at 5367,2158.76 h60
  text "Enter Place Line mode (keyboard pl)" at 5577,2034.71 h60
  text "keyboard jo to jump to origin, hit enter" at 5577,1910.65 h60
  text "keyboard jl to jump to location, set x to 6000, hit enter twice" at 5577,1786.59 h60
  text "keyboard jl to jump to location, set x to 6000 and y to 4000, hit enter twice" at 5577,1662.53 h60
  text "keyboard jl to jump to location, set x to 0 and y to 4000, hit enter twice" at 5577,1538.47 h60
  text "keyboard jo to jump to origin, hit enter" at 5577,1414.41 h60
  text "Hit ESC twice to exit place line mode" at 5577,1290.35 h60
  text "Select lines on M1 Board Outline" at 5367,1146.3 h60
  text "IOUT" at 2368,1126 h40
  text "Menu Design|Board Shape|Define from Selected Objects (keyboard dsd)" at 5367,1042.24 h60
  text "To define a Keep-Out that mirrors the board outline:" at 5252,918.18 h60
  text "Menu Design|Board Shape|Create Primitives From Board Shape (keyboard dsp)" at 5367,794.12 h60
  text "GND" at 2380,761 h40
  text "Set the Keep-Out Layer as the layer, set width as preferred" at 5577,670.06 h60
  text "Ensure Route Tool Outline is selected, hit enter" at 5577,546 h60
  text "If you re-size the board, don't forget to move the drill table strings on the" at 5252,223 h60
  text "Drill Drawing Layer...they should be just to the right of your board shape" at 5445,117 h60
  text "+24V" at 1347,35 h40
  text "GND" at 1822,35 h40
  text ".Layer_Name" at 529,-858.49 h60
Bottom Overlay:
  text ".Layer_Name" at 529,-858.49 h60
Top Paste:
  text ".Layer_Name" at 529,-858.49 h60
Bottom Paste:
  text ".Layer_Name" at 529,-858.49 h60
Top Solder:
  text ".Layer_Name" at 529,-858.49 h60
  text ".Layer_Name" at 529,-858.49 h60
Bottom Solder:
  text ".Layer_Name" at 529,-858.49 h60
Drill Guide:
  text ".Layer_Name" at 529,-858.49 h60
M1 Board Outline:
  the board outline again, w10
  text ".Layer_Name" at 529,-858.49 h60
M2 Board Dimensions:
  rectangle: 77,-400 452,-275
  rectangle: -48,-275 77,-150
  lines w7: -48,-275 952,-275 ; 77,-400 77,-150 ; 202,-400 202,-150 ; 452,-400 452,-150 ; 702,-400 702,-150 ; -48,-400 -48,-150 952,-150 952,-400 -48,-400
  text ".Layer_Name" at 529,-858.49 h60
M3 3D STEP Top:
  text ".Layer_Name" at 529,-858.49 h60
M4 3D STEP Bottom:
  text ".Layer_Name" at 529,-858.49 h60
M5 Assembly Top:
  lines w10: -340,-930.17 6260,-930.17 ; -340,-726.83 6262,-726.83 ; -340,-523.5 -340,-1133.5 3665,-1133.5 6262,-1133.5 6262,-523.5 -339.5,-523.5 -339.5,-1133.5 1236,-1133.5 ; 2125,-1133.5 2125,-523.5 ; 3392,-726.83 3392,-523.5 ; 4232,-726.83 4232,-523.5 ; 4854,-1140 4854,-937.17
  text "COMPONENTS MARKED 'DNP' SHOULD NOT BE POPULATED." at 1105.5,-318.5 h60
  text "ASSEMBLY VARIANT:" at 1105,-434 h60
  text ".VariantName" at 2141,-434 h60
  text "PCB VIEWED FROM TOP SIDE" at -276.5,-655.67 h60
  text "BOARD #:" at 2200,-655.67 h60
  text ".PRJ_Number" at 2745.5,-655.67 h60
  text "REV:" at 3590,-655.67 h60
  text ".PCB_Rev" at 3881.5,-655.67 h60
  text "SVN REV:" at 4428,-655.67 h60
  text ".VersionControl_RevNumber" at 4934,-655.67 h60
  text "TID #:" at 2200,-859 h60
  text ".TID" at 2745.5,-859 h60
  text "PLOT NAME =" at -276.5,-1064.34 h60
  text ".plot_File_Name" at 529,-1064.34 h60
  text "GENERATED    :" at 2202,-1064.34 h60
  text ".Print_Date" at 3071.5,-1064.34 h60
  text ".Print_Time" at 3800.5,-1064.34 h60
  text "TEXAS INSTRUMENTS" at 5065,-1064.34 h60
M6 Assembly Bottom:
  lines w10: -340.5,-727.33 6261.5,-727.33 ; -338.5,-930.67 6261.5,-930.67 ; 1067.5,-1140.5 1067.5,-937.67 ; 1689.5,-727.33 1689.5,-524 ; 2529.5,-727.33 2529.5,-524 ; 3796.5,-1134 3796.5,-524 ; 4685.5,-1134 6261,-1134 6261,-524 -340.5,-524 -340.5,-1134 2256.5,-1134 6261.5,-1134 6261.5,-524
  text "COMPONENTS MARKED 'DNP' SHOULD NOT BE POPULATED." at 6054,-318 h60
  text ".VariantName" at 5010,-434 h60
  text "ASSEMBLY VARIANT:" at 6049,-434 h60
  text ".VersionControl_RevNumber" at 987.5,-656.17 h60
  text "SVN REV:" at 1493.5,-656.17 h60
  text ".PCB_Rev" at 2040,-656.17 h60
  text "REV:" at 2331.5,-656.17 h60
  text ".PRJ_Number" at 3176,-656.17 h60
  text "BOARD #:" at 3721.5,-656.17 h60
  text "PCB VIEWED FROM BOTTOM SIDE" at 6198,-656.17 h60
  text ".TID" at 3176,-859.5 h60
  text "TID #:" at 3721.5,-859.5 h60
  text "TEXAS INSTRUMENTS" at 856.5,-1064.84 h60
  text ".Print_Time" at 2121,-1064.84 h60
  text ".Print_Date" at 2850,-1064.84 h60
  text "GENERATED    :" at 3719.5,-1064.84 h60
  text ".plot_File_Name" at 5392.5,-1064.84 h60
  text "PLOT NAME =" at 6198,-1064.84 h60
M9 Title Sheet:
  drawing of 57 lines, arcs and shapes, not listed
  text "1" at 691.84,8036.5 h70
  text "2" at 3187.5,8036.5 h70
  text "3" at 5676.84,8036.5 h70
  text "4" at 8183.51,8036.5 h70
  text "5" at 10682.5,8036.5 h70
  text "6" at 13187.5,8036.5 h70
  text "A" at -464.5,6893.5 h70
  text "A" at 14335.5,6893.5 h70
  text "B" at -464.5,4513.5 h70
  text "B" at 14335.5,4513.5 h70
  text "C" at -464.5,2138.5 h70
  text "C" at 14335.5,2138.5 h70
  text "PROJECT TITLE:" at 11295.5,277.5 h45
  text ".PRJ_Title" at 11345.5,144.17 h70
  text "DESIGNED FOR:" at 11295.5,-23.5 h45
  text ".PRJ_Customer" at 11345.5,-163.5 h70
  text "D" at -464.5,-231.5 h70
  text "D" at 14335.5,-231.5 h70
  text "FILE NAME:" at 11295.5,-323.5 h45
  text ".PCB_File_Name_No_Path" at 11345.5,-443.5 h70
  text "Texas Instruments (TI) and/or its licensors do not warrant the accuracy or completeness of this specification" at 6326,-605.34 h45
  text "ENGINEER:" at 11295.5,-613.5 h45
  text "LAYOUT BY:" at 12800.5,-613.5 h45
  text "or any information contained therein. TI and/or its licensors do not warrant that this design will meet" at 6281.01,-718 h45
  text ".PRJ_Engineer" at 11345.5,-768.49 h70
  text ".PCB_Layout" at 12851,-768.49 h70
  text "the specifications, will be suitable for your application or fit for any particular purpose, or will operate in" at 6281.01,-830.67 h45
  text ".Layer_Name" at 529,-858.49 h60
  text "ALTIUM DESIGNER VERSION:" at 12800.5,-923.5 h45
  text "an implementation. TI and/or its licensors do not warrant that the design is production worthy. You should" at 6281.01,-943.33 h45
  text "completely validate and test your design implementation to confirm the system functionality for your application." at 6326,-1056 h45
  text ".print_Scale" at 11345.5,-1056.83 h70
  text ".Application_BuildNumber" at 12851,-1056.83 h70
  text "1" at 691.84,-1263.5 h70
  text "2" at 3187.5,-1263.5 h70
  text "3" at 5676.84,-1263.5 h70
  text "4" at 8183.51,-1263.5 h70
  text "5" at 10682.5,-1263.5 h70
  text "6" at 13187.5,-1263.5 h70
M10 Fab Notes:
  drawing of 189 lines, arcs and shapes, not listed
  text "DESIGN INFORMATION" at 12333.02,6028 h60
  text "MIN. TRACK WIDTH:" at 11688.46,5848 h60
  text "8" at 12784.7,5848 h60
  text "MIL" at 12939.46,5848 h60
  text "MIN. CLEARANCE:" at 11688.46,5716 h60
  text "0.2" at 12724.7,5716 h60
  text "mm" at 12939.46,5716 h60
  text "MIN. VIA PAD SIZE:" at 11688.46,5584 h60
  text "24" at 12754.71,5584 h60
  text "MIL" at 12939.46,5584 h60
  text "0.05mm (2MIL)" at 12383.46,5442.29 h60
  text "MINIMUM ANNULAR RING" at 11359.23,5438 h60
  text "EXTERNAL" at 13091.46,5438 h60
  text "PER" at 11559.23,5320 h60
  text "IPC-D-275 CLASS 2 LEVEL C" at 11779.23,5320 h60
  text "MIL, HOLES" at 13267.46,5207.71 h60
  text "+/-" at 12875,5207 h60
  text "+/-" at 13729,5207 h60
  text "REGISTRATION TOLERANCES:" at 11359.23,5202 h60
  text "METAL" at 12559,5202 h60
  text "5" at 13135.2,5202 h60
  text "3" at 13968.2,5202 h60
  text "MIL" at 14084.46,5202 h60
  text "+/-" at 13729,5089 h60
  text "HOLE SIZE TOLERANCE (UNLESS OTHERWISE SPECIFIED):" at 11359.23,5084 h60
  text "3" at 13968.2,5084 h60
  text "MIL" at 14084.46,5084 h60
  text "MATERIAL:" at 11284.46,4874.54 h60
  text "FR-4 High Tg" at 12270.9,4734.21 h60
  text "FR-408" at 11705.46,4725.64 h60
  text "OTHER" at 13193.46,4725.64 h60
  text "X" at 12116,4722 h60
  text "62 MIL (1.6mm) +/-10%" at 12025.56,4562.92 h60
  text "THICKNESS:" at 11359.23,4558.64 h60
  text "X" at 11897.4,4558.64 h60
  text "OTHER" at 13310.46,4558.64 h60
  text "TOLERANCE:" at 11359.23,4400.64 h60
  text "X" at 12198.53,4400.64 h60
  text "ANSI IPC-6012 TYPE 3 CLASS 2" at 12385.48,4400.64 h60
  text "OTHER +/-" at 12385.46,4244.64 h60
  text "BOW & TWIST:" at 11359.23,4087.64 h60
  text "X" at 12198.53,4087.64 h60
  text "ANSI IPC-6012 TYPE 3 CLASS 2" at 12385.48,4087.64 h60
  text "OTHER +/-" at 12385.46,3929.13 h60
  text "DRILLING:" at 11284.46,3790.64 h60
  text "REFERENCE:" at 11359.23,3673.64 h60
  text "X" at 12007.46,3673.64 h60
  text "AS SHOWN" at 12194.46,3673.64 h60
  text "X" at 12908.46,3673.64 h60
  text "NC_DRILL FILES" at 13045.46,3673.64 h60
  text "PTH MIN COPPER THICKNESS:" at 11359.23,3515.64 h60
  text "X" at 12709.46,3515.64 h60
  text "1MIL" at 12846.46,3515.64 h60
  text "OTHER" at 13343.46,3515.64 h60
  text "BOARD FINISH:" at 11284.46,3356.64 h60
  text "SILKSCREEN:" at 11439.68,3238.64 h60
  text "X" at 12388.46,3238.64 h60
  text "TOP" at 12514.46,3238.64 h60
  text "X" at 12898.46,3238.64 h60
  text "BOTTOM" at 13025.46,3238.64 h60
  text "SILKSCREEN COLOR:" at 11439.68,3071.64 h60
  text "X" at 12387.42,3071.64 h60
  text "WHITE" at 12514.46,3071.64 h60
  text "OTHER" at 13025.46,3071.64 h60
  text "X" at 12518.42,2912.44 h60
  text "GREEN" at 12645.46,2912.44 h60
  text "OTHER" at 13263.46,2912.44 h60
  text "SOLDER RESIST COLOR:" at 11439.68,2901.64 h60
  text "X" at 12518.42,2742.44 h60
  text "MATTE" at 12645.46,2742.44 h60
  text "SEMI-GLOSS" at 13263,2741.8 h60
  text "IMMERSION GOLD (ENIG)" at 12345.46,2553.92 h60
  text "ENEPIG" at 13683,2550.64 h60
  text "SURFACE FINISH:" at 11284.46,2549.64 h60
  text "X" at 12158.51,2549.64 h60
  text "IMM. TIN/SILVER OR EQUIV" at 11614,2392.64 h60
  text "OTHER" at 13045.46,2392.64 h60
  text "ARRAY/PANEL:" at 11284.46,2213.64 h60
  text "CUT AND TRIM PER M1 BOARD OUTLINE" at 12345.46,2209.35 h60
  text "N.C. ROUTE" at 12345.46,2057.64 h60
  text "X" at 13024.46,2057.64 h60
  text "V. SCORE" at 13211.46,2057.64 h60
  text "CERTIFICATION:" at 11284.46,1920.64 h60
  text "MATERIALS AND WORKMANSHIP FOR ALL PCBS" at 12009.46,1920.64 h60
  text "TO MEET OR EXCEED THE REQUIREMENTS OF:" at 12009.46,1822.64 h60
  text "X" at 11635.96,1686.13 h60
  text "ANSI IPC-A-600F CLASS ->" at 11774.96,1686.13 h60
  text "X" at 13414.02,1686.13 h60
  text "2" at 13532.96,1686.14 h60
  text "1" at 13217.96,1684.64 h60
  text "3" at 13886.96,1684.64 h60
  text "X" at 11638.02,1526.64 h60
  text "UL 94V-0" at 11774.96,1526.64 h60
  text "X" at 12450.02,1526.64 h60
  text "RoHS" at 12586.96,1526.64 h60
  text "OTHER" at 13231.36,1526.64 h60
  text "PER ORDER" at 13628.42,1526.64 h60
  text "ADDITIONAL REQUIREMENTS:" at 11284.46,1385.64 h60
  text "MICROSECTION:" at 11359.23,1270.64 h60
  text "YES" at 12264.96,1270.64 h60
  text "REQUIRED" at 13126.46,1114.49 h60
  text "BARE BOARD ELEC. TEST:" at 11359.23,1111.64 h60
  text "NONE" at 12664.96,1111.64 h60
  text "X" at 12999.46,1111.64 h60
  text "PER ORDER" at 13718.46,1111.64 h60
  text "MANUFACTURER'S UL:" at 11359.23,954.64 h60
  text "RAIL" at 12524.96,950.35 h60
  text "METAL" at 13016.77,950.35 h60
  text "X" at 13392,950 h60
  text "SILK" at 13528.46,950.35 h60
  text ".Layer_Name" at 529,-858.49 h60
M11 Gerber Information:
  lines w10: -340,-930.17 6260,-930.17 ; -340,-726.83 6262,-726.83 ; -340,-523.5 -340,-1133.5 3665,-1133.5 6262,-1133.5 6262,-523.5 -339.5,-523.5 -339.5,-1133.5 1236,-1133.5 ; 2125,-1133.5 2125,-523.5 ; 3392,-726.83 3392,-523.5 ; 4232,-726.83 4232,-523.5 ; 4854,-1140 4854,-937.17
  text "ALL ARTWORK VIEWED FROM TOP SIDE" at -276.5,-655.67 h60
  text "BOARD #:" at 2200,-655.67 h60
  text ".PRJ_Number" at 2745.5,-655.67 h60
  text "REV:" at 3590,-655.67 h60
  text ".PCB_Rev" at 3881.5,-655.67 h60
  text "SVN REV:" at 4428,-655.67 h60
  text ".VersionControl_RevNumber" at 4934,-655.67 h60
  text "LAYER NAME =" at -276.5,-858.49 h60
  text "TID #:" at 2200,-859 h60
  text ".TID" at 2745.5,-859 h60
  text "PLOT NAME =" at -276.5,-1064.34 h60
  text ".plot_File_Name" at 529,-1064.34 h60
  text "GENERATED    :" at 2202,-1064.34 h60
  text ".Print_Date" at 3071.5,-1064.34 h60
  text ".Print_Time" at 3800.5,-1064.34 h60
  text "TEXAS INSTRUMENTS" at 5065,-1064.34 h60
M12 Stackup:
  drawing of 191 lines, arcs and shapes, not listed
  text "Layer" at 9742.58,7830 h60
  text "Name" at 10152.49,7830 h60
  text "Material" at 11082.23,7830 h60
  text "Thickness" at 11942,7830 h60
  text "Constant" at 12591.84,7830 h60
  text "Board Layer Stack" at 13161.7,7830 h60
  text "1" at 9742.58,7710 h60
  text "Top Overlay" at 10152.49,7710 h60
  text "2" at 9742.58,7590 h60
  text "Top Solder" at 10152.49,7590 h60
  text "Solder Resist" at 11082.23,7590 h60
  text "0.40mil" at 11942,7590 h60
  text "3.5" at 12591.84,7590 h60
  text "3" at 9742.58,7470 h60
  text "Top Layer" at 10152.49,7470 h60
  text "Copper" at 11082.23,7470 h60
  text "1.40mil" at 11942,7470 h60
  text "4" at 9742.58,7350 h60
  text "Dielectric1" at 10152.49,7350 h60
  text "FR-4" at 11082.23,7350 h60
  text "59.20mil" at 11942,7350 h60
  text "4.8" at 12591.84,7350 h60
  text "5" at 9742.58,7230 h60
  text "Bottom Layer" at 10152.49,7230 h60
  text "Copper" at 11082.23,7230 h60
  text "1.40mil" at 11942,7230 h60
  text "6" at 9742.58,7110 h60
  text "Bottom Solder" at 10152.49,7110 h60
  text "Solder Resist" at 11082.23,7110 h60
  text "0.40mil" at 11942,7110 h60
  text "3.5" at 12591.84,7110 h60
  text "7" at 9742.58,6990 h60
  text "Bottom Overlay" at 10152.49,6990 h60
  text ".Layer_Name" at 529,-858.49 h60
M13 Component Bodies Top:
  text ".Layer_Name" at 529,-858.49 h60
M14 Component Bodies Bottom:
  text ".Layer_Name" at 529,-858.49 h60
M15 Courtyards Top:
  text ".Layer_Name" at 529,-858.49 h60
M16 Courtyards Bottom:
  text ".Layer_Name" at 529,-858.49 h60
Drill Drawing:
  circle w10: c5500.72,3303.23 r13.24
  circle w10: c5500.72,3303.23 r22.07
  lines w10: 5478.65,2883.88 5522.79,2883.88 5522.79,2928.02 5478.65,2928.02 5478.65,2883.88 ; 5478.65,2994.23 5489.68,2994.23 5500.72,2983.2 5511.75,2994.23 5522.79,2994.23 5511.75,3005.27 5522.79,3016.3 5511.75,3016.3 5500.72,3027.34 5489.68,3016.3 5478.65,3016.3 5489.68,3005.27 5478.65,2994.23 ; 5478.65,3082.52 5522.79,3082.52 5522.79,3126.66 5478.65,3126.66 5478.65,3082.52 ; 5478.65,3203.91 5500.72,3181.84 5522.79,3203.91 5500.72,3225.98 5478.65,3203.91 ; 5487.47,3091.34 5513.96,3091.34 5513.96,3117.83 5487.47,3117.83 5487.47,3091.34
  lines w12: 5438,2854.08 7326.45,2854.08 ; 5438,3350.68 7326.45,3350.68 ; 5753.49,2754.76 5753.49,3450 ; 6070.58,2754.76 6070.58,3450 ; 6692.22,2754.76 6692.22,3450 ; 6936.41,2754.76 6936.41,3450 ; 5438,2754.76 7326.45,2754.76 7326.45,3450 5438,3450 5438,2754.76
  text "Symbol" at 5497.59,3380.48 h72
  text "Quantity" at 5783.28,3380.48 h72
  text "Finished Hole Size" at 6100.38,3380.48 h72
  text "Plated" at 6722.02,3380.48 h72
  text "Hole Type" at 6966.21,3380.48 h72
  text "4" at 5783.28,3281.16 h60
  text "10.00mil (0.254mm)" at 6100.38,3281.16 h60
  text "PTH" at 6722.02,3281.16 h60
  text "Round" at 6966.21,3281.16 h60
  text "83" at 5783.28,3181.84 h60
  text "15.00mil (0.381mm)" at 6100.38,3181.84 h60
  text "PTH" at 6722.02,3181.84 h60
  text "Round" at 6966.21,3181.84 h60
  text "5" at 5783.28,3082.52 h60
  text "28.00mil (0.711mm)" at 6100.38,3082.52 h60
  text "PTH" at 6722.02,3082.52 h60
  text "Round" at 6966.21,3082.52 h60
  text "10" at 5783.28,2983.2 h60
  text "28.74mil (0.730mm)" at 6100.38,2983.2 h60
  text "PTH" at 6722.02,2983.2 h60
  text "Round" at 6966.21,2983.2 h60
  text "4" at 5783.28,2883.88 h60
  text "50.00mil (1.270mm)" at 6100.38,2883.88 h60
  text "PTH" at 6722.02,2883.88 h60
  text "Round" at 6966.21,2883.88 h60
  text "106 Total" at 5783.28,2784.56 h60
  text ".Layer_Name" at 529,-858.49 h60

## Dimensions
-48,0 to 0,2000 on M2 Board Dimensions
-48,0 to 2552,0 on M2 Board Dimensions
-48,-400 to 952,-400 on M2 Board Dimensions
